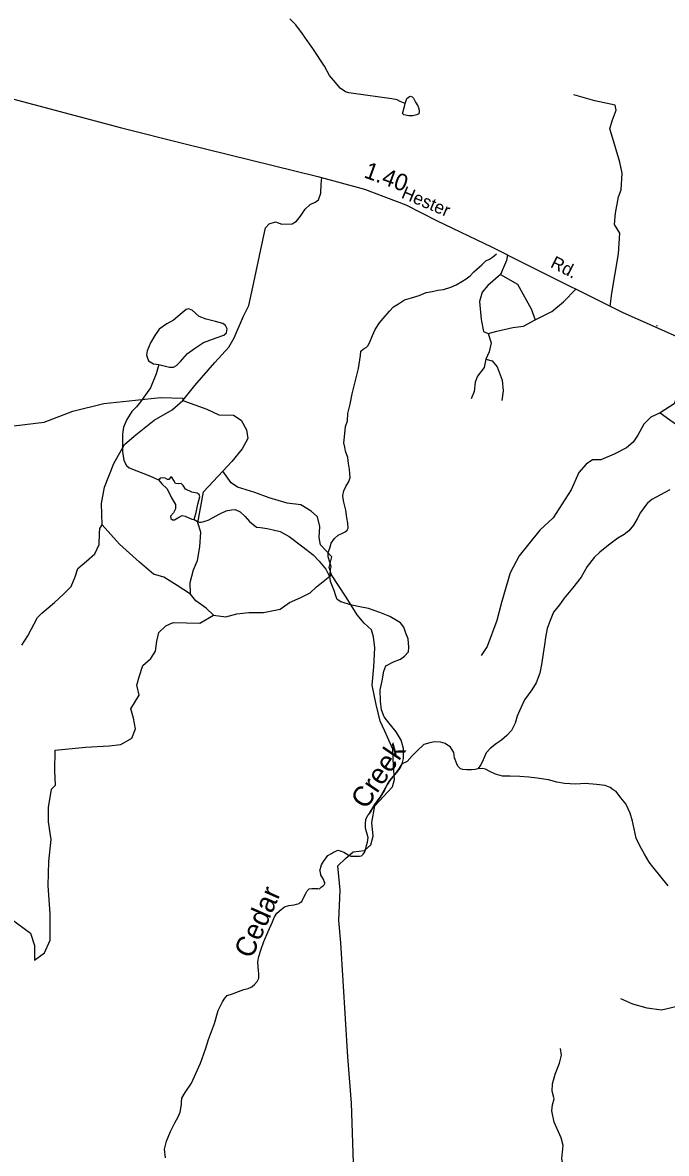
# Model space of a CAD drawing. Extents: x 2056842 to 2160602, y 826753 to 1016856.
# Drawn here: x 2105136 to 2109914, y 872458 to 880850 of the extents above; entities that cross this region are included whole.
import ezdxf

# ---------------------------------------------------------------- set-up
doc = ezdxf.new("R2010")
doc.units = 0
for name, color, linetype in [('Exist Hydrographic Creek Single Shore', 7, 'Continuous'), ('Exist Hydrographic Creek Single Shore Label', 7, 'Continuous'), ('Exist Hydrographic Misc Water Feature', 7, 'Continuous'), ('Exist Road Non-System Type 51', 7, 'Continuous'), ('Exist Road Secondary Mileage Hundredths English Label', 7, 'Continuous'), ('Exist Road Secondary Type 51 Attributed', 7, 'Continuous'), ('Exist Road Secondary Type 51 Label', 7, 'Continuous')]:
    doc.layers.add(name, color=color, linetype=linetype)

msp = doc.modelspace()

# ---------------------------------------------------------------- linework, layer by layer
at = {"layer": 'Exist Hydrographic Creek Single Shore'}
for points in [[(2107975.1, 880248.9), (2107938.9, 880263.4), (2107916.8, 880275.4), (2107876.8, 880285.2), (2107592.8, 880324.4), (2107556.9, 880328.2), (2107532.9, 880336.2), (2107492.5, 880364.1), (2107458.7, 880405.9), (2107414.4, 880457.8), (2107376, 880525.6), (2107289.9, 880657.4), (2107265.5, 880693.3), (2107213.2, 880767.1), (2107163.4, 880832.9), (2107119.1, 880876.8)], [(2107413.7, 876738), (2107417.7, 876754.3), (2107421.7, 876790.3), (2107425.4, 876810.2), (2107417.3, 876846.2), (2107403.3, 876886.1), (2107403.3, 876918), (2107415.2, 876950.2), (2107427.1, 876986.1), (2107450.7, 877020.3), (2107478.8, 877046.3), (2107510.6, 877060.5), (2107530.8, 877070.5), (2107544.5, 877082.4), (2107552.8, 877098.6), (2107548.6, 877134.5), (2107542.5, 877174.3), (2107534.2, 877230.6), (2107520, 877290.3), (2107512, 877332.4), (2107511.8, 877340.3), (2107519.7, 877374.3), (2107535.8, 877406.4), (2107555.5, 877438.5), (2107567.3, 877470.4), (2107565.4, 877502.6), (2107561.1, 877534.5), (2107555.1, 877578.6), (2107549.2, 877622.4), (2107532.8, 877670.3), (2107526.8, 877700.2), (2107520.6, 877732.2), (2107524.5, 877776.4), (2107532.3, 877852.4), (2107548.2, 877894.4), (2107550, 877948.5), (2107565.9, 878018.4), (2107581.6, 878094.5), (2107628.8, 878282.5), (2107642.6, 878378.7), (2107646.5, 878410.7), (2107662.6, 878426.5), (2107686.5, 878438.8), (2107698.5, 878450.7), (2107710.5, 878472.8), (2107732.3, 878528.7), (2107751.9, 878573), (2107783.7, 878620.9), (2107811.6, 878653.1), (2107859.7, 878709.2), (2107889.5, 878739.4), (2107925.5, 878763.3), (2107971.4, 878793.5), (2108023.2, 878807.8), (2108079.3, 878823.7), (2108130.9, 878846), (2108175.1, 878854.2), (2108218.9, 878864.5), (2108259, 878868.6), (2108314.9, 878886.8), (2108354.9, 878902.7), (2108396.8, 878928.7), (2108428.6, 878947.1), (2108456.7, 878971.1), (2108484.5, 878999.1), (2108544.4, 879053.3), (2108574.1, 879081.6), (2108600.3, 879093.5), (2108624.3, 879109.4), (2108654, 879133.7)], [(2107953.9, 875348.1), (2107963.9, 875389.9), (2107963.5, 875464), (2107945.4, 875523.8), (2107909.3, 875585.9), (2107855.2, 875653.6), (2107819.1, 875697.7), (2107798.8, 875749.6), (2107792.6, 875813.4), (2107790.4, 875897.4), (2107804.3, 875965.4), (2107817.9, 876037.6), (2107831.8, 876077.4), (2107887.5, 876105.7), (2107939.5, 876126), (2107969.5, 876148), (2107999.3, 876179.9), (2108003.3, 876215.9), (2107997, 876276.1), (2107980.9, 876320), (2107964.7, 876364), (2107940.8, 876395.7), (2107916.8, 876409.6), (2107860.7, 876441.6), (2107786.5, 876473.3), (2107702.5, 876501), (2107638.5, 876514.8), (2107578.3, 876526.5), (2107498.5, 876552.5), (2107470.3, 876568.5), (2107460.3, 876596.2), (2107448, 876636.2), (2107435.9, 876666.3), (2107421.8, 876702), (2107417.7, 876726.1), (2107413.7, 876738)], [(2108514.3, 875311.9), (2108494.6, 875308), (2108468.3, 875303.9), (2108432.3, 875303.7), (2108402.3, 875307.8), (2108386.3, 875311.4), (2108365.8, 875331.6), (2108357.8, 875349.4), (2108342.2, 875393.6), (2108335.7, 875433.5), (2108311.7, 875473.3), (2108273.3, 875500.9), (2108237.9, 875509.2), (2108193.4, 875513), (2108157.7, 875504.7), (2108114, 875492.6), (2108063.8, 875446.3), (2108026, 875408.6), (2107990.2, 875366.1), (2107953.9, 875348.1)], [(2107652.1, 874667.3), (2107664.1, 874679.2), (2107672.3, 874691.1), (2107680.2, 874711.3), (2107688.1, 874743.3), (2107695.8, 874767.4), (2107699.8, 874803.4), (2107693.8, 874827.2), (2107689.5, 874843.4), (2107681.5, 874871.1), (2107681.6, 874903.2), (2107683.2, 874935.4), (2107695.3, 874963.3), (2107699.3, 874967.2), (2107707.1, 874979.2), (2107719.2, 874995.3), (2107727.1, 875011.2), (2107748.9, 875047.5), (2107788.7, 875101.5), (2107820.6, 875153.7), (2107844.5, 875197.8), (2107860.5, 875225.7), (2107910.3, 875286), (2107934.2, 875318), (2107953.9, 875348.1)], [(2106197.5, 872424.9), (2106189.3, 872489), (2106193.3, 872509), (2106203, 872548.8), (2106234.7, 872621), (2106266.5, 872685), (2106290.4, 872729.1), (2106304.3, 872765.2), (2106314.3, 872821.1), (2106314, 872837.2), (2106317.9, 872869.3), (2106342, 872909.1), (2106389.7, 872979.3), (2106421.4, 873051.5), (2106455.1, 873127.6), (2106492.7, 873231.8), (2106516.5, 873303.9), (2106560.3, 873422), (2106587.9, 873517.9), (2106605.7, 873554), (2106619.7, 873581.9), (2106635.7, 873610.1), (2106653.5, 873630.1), (2106693.5, 873642.4), (2106737.5, 873660.5), (2106777.5, 873674.5), (2106809.5, 873682.7), (2106837.3, 873694.9), (2106857.3, 873710.9), (2106877.2, 873734.7), (2106881.3, 873742.9), (2106889.2, 873758.8), (2106889.2, 873790.9), (2106887, 873814.9), (2106885, 873842.9), (2106880.8, 873878.7), (2106888.5, 873918.9), (2106904.6, 873966.8), (2106926.3, 874031), (2106958, 874105.1), (2106989.7, 874177), (2107005.8, 874213.1), (2107023.5, 874241.3), (2107055.6, 874269.5), (2107079.6, 874289.3), (2107111.6, 874297.5), (2107151.4, 874303.6), (2107169.5, 874307.8), (2107187.3, 874311.7), (2107195.4, 874319.7), (2107207.4, 874327.7), (2107223.1, 874359.9), (2107239.1, 874388.1), (2107249, 874407.9), (2107263.1, 874422), (2107283.2, 874423.9), (2107315, 874424.2), (2107327.2, 874424.3), (2107338.9, 874422.1), (2107346.9, 874428.2), (2107355, 874436.2), (2107366.9, 874444.2), (2107375, 874452.2), (2107378.7, 874460.3), (2107378.9, 874468.2), (2107374.8, 874476.5), (2107370.8, 874488.4), (2107358.7, 874508.3), (2107350.5, 874524.2), (2107346.7, 874544.3), (2107342.6, 874554.2), (2107354.4, 874600.3), (2107368.4, 874624.3), (2107400.1, 874668.2), (2107428.3, 874684.4), (2107444.3, 874692.6), (2107460.2, 874700.4), (2107476.1, 874708.7), (2107492.1, 874704.7), (2107520, 874692.7), (2107540.1, 874680.8), (2107552.2, 874674.9), (2107572.3, 874663), (2107580.1, 874662.9), (2107608.3, 874662.9), (2107620.2, 874663), (2107636.2, 874663), (2107652.1, 874667.3)]]:
    msp.add_lwpolyline(points, dxfattribs=at)
at = {"layer": 'Exist Hydrographic Misc Water Feature'}
msp.add_line((2109840.1, 878603.3), (2109843.6, 878596.9), dxfattribs=at)
for points in [[(2107975.1, 880248.9), (2107988.5, 880285.3), (2108006.7, 880302.4), (2108015.2, 880303.6), (2108026.2, 880299.9), (2108035.9, 880287.8), (2108051.7, 880258.6), (2108068.7, 880231.8), (2108076, 880212.4), (2108079.7, 880190.5), (2108076, 880173.5), (2108062.6, 880164.9), (2108031, 880158.9), (2108003.1, 880158.9), (2107965.4, 880164.9), (2107956.9, 880172.2), (2107956.9, 880183.2), (2107969.1, 880227), (2107975.1, 880248.9)], [(2106146.8, 878312.3), (2106227.1, 878292.8), (2106255, 878294), (2106279.3, 878306.2), (2106308.5, 878335.4), (2106359.6, 878393.7), (2106411.8, 878430.2), (2106477.4, 878475.2), (2106572.3, 878510.5), (2106630.6, 878531.2), (2106648.8, 878548.2), (2106653.7, 878576.2), (2106642.7, 878602.9), (2106622.1, 878617.5), (2106567.4, 878632.1), (2106498.1, 878647.9), (2106445.8, 878668.6), (2106393.6, 878716), (2106368.1, 878725.7), (2106348.6, 878720.9), (2106320.7, 878695.3), (2106255, 878641.8), (2106206.4, 878613.9), (2106150.5, 878573.7), (2106117.7, 878528.7), (2106084.9, 878474), (2106060.6, 878413.2), (2106054.5, 878385.2), (2106059.3, 878367), (2106070.3, 878339), (2106106.7, 878317.1), (2106146.8, 878312.3)], [(2106146.8, 878312.3), (2106127.4, 878244.1), (2106086.1, 878140.5), (2106011.9, 878035.9), (2105980.3, 877999.5), (2105946.4, 877963.5), (2105908.9, 877903.5), (2105885.1, 877847.4), (2105876.9, 877795.6), (2105877.1, 877727.4), (2105877.1, 877667.3), (2105888, 877599.4), (2105907.4, 877564.1), (2105925.6, 877545.8), (2106084.9, 877483.8), (2106145.6, 877457.1)], [(2106409.4, 877161.5), (2106422.8, 877213.8), (2106437.3, 877275.9), (2106450.7, 877329.4), (2106445.8, 877347.6), (2106431.3, 877358.6), (2106391.2, 877365.9), (2106343.8, 877387.7), (2106328, 877414.5), (2106313.4, 877429.1), (2106292.7, 877427.9), (2106269.6, 877430.3), (2106258.7, 877452.2), (2106246.5, 877471.7), (2106235.6, 877479), (2106230.7, 877471.7), (2106222.2, 877459.5), (2106211.3, 877459.5), (2106193, 877468), (2106173.6, 877470.4), (2106157.8, 877468), (2106151.7, 877461.9), (2106145.6, 877457.1)], [(2106145.6, 877457.1), (2106169.9, 877427.9), (2106207.6, 877390.2), (2106241.7, 877322.1), (2106269.6, 877274.6), (2106270.8, 877241.8), (2106256.2, 877212.6), (2106234.4, 877187.1), (2106235.6, 877168.8), (2106247.7, 877159.1), (2106263.5, 877160.3), (2106289.1, 877174.9), (2106320.7, 877191.9), (2106342.5, 877187.1), (2106392.4, 877165.2), (2106409.4, 877161.5)], [(2109940.2, 877383.1), (2109869.7, 877345.4), (2109806.5, 877311.4), (2109773.7, 877284.6), (2109760.4, 877268.8), (2109722, 877213.4), (2109698.2, 877167.5), (2109670.4, 877119.4), (2109634.3, 877079.4), (2109600.6, 877051.2), (2109554.7, 877022.8), (2109484.8, 876973), (2109419.2, 876920.4), (2109379, 876880.3), (2109325.5, 876814.2), (2109281.4, 876734), (2109217.6, 876651.9), (2109156.1, 876577.7), (2109120.4, 876529.5), (2109076.5, 876473.6), (2109052.5, 876413.6), (2109028.5, 876353.5), (2109017.3, 876285.5), (2109009.5, 876233.5), (2108999.6, 876169.2), (2108987.7, 876085.4), (2108973.6, 876021.4), (2108948, 875951.4), (2108916.4, 875899), (2108860.8, 875823.1), (2108822.7, 875742.8), (2108807.3, 875702.9), (2108791.3, 875650.5), (2108765.3, 875596.9), (2108729.6, 875560.5), (2108689.6, 875524.3), (2108653.7, 875500.2), (2108605.5, 875464), (2108576, 875432), (2108554.3, 875378.1), (2108538.1, 875342), (2108514.3, 875311.9)], [(2106409.4, 877161.5), (2106432.8, 877147.3), (2106448.6, 877143.3), (2106460.9, 877143.1), (2106480.8, 877147.3), (2106512.6, 877157.6), (2106549.1, 877177.5), (2106594.8, 877201.5), (2106646.7, 877225.6), (2106686.9, 877233.8), (2106714.7, 877236.1), (2106750.8, 877220.1), (2106786.5, 877184.2), (2106820.8, 877148.1), (2106873, 877104.5), (2106900.7, 877102.8), (2106951, 877094.8), (2106994.6, 877084.9), (2107047.1, 877072.9), (2107115.2, 877037.4), (2107215.3, 876959.8), (2107291.6, 876899.9), (2107337.5, 876854), (2107386.1, 876794.3), (2107413.8, 876738.2)], [(2107953.9, 875348.1), (2107934.6, 875318.1), (2107910.4, 875286.1), (2107860.6, 875226), (2107844.8, 875197.9), (2107820.8, 875153.6), (2107788.8, 875101.7), (2107749.2, 875047.6), (2107727.5, 875011.6), (2107719.3, 874995.4), (2107707.4, 874979.7), (2107699.4, 874967.5)], [(2109926.9, 874444.9), (2109812.5, 874584), (2109786.2, 874620.1), (2109752, 874678.1), (2109715.9, 874741.9), (2109689.4, 874797.9), (2109675.3, 874865.8), (2109663.2, 874923.6), (2109645.1, 874983.5), (2109629.4, 875015.6), (2109612.7, 875051.4), (2109577.1, 875097.3), (2109540.6, 875143), (2109520.3, 875157.1), (2109496.7, 875173.3), (2109458.5, 875189.2), (2109394.4, 875196.8), (2109310.3, 875202.7), (2109242.4, 875198.4), (2109158.3, 875204.1), (2109100.1, 875213.8), (2109038.6, 875229.7), (2108954.1, 875243.2), (2108894.2, 875251.1), (2108826.6, 875254.9), (2108754.6, 875256.8), (2108698.4, 875258.5), (2108646.3, 875272.4), (2108602.5, 875292.1), (2108570.3, 875310.3), (2108550.4, 875314.1), (2108514.3, 875311.9)]]:
    msp.add_lwpolyline(points, dxfattribs=at)
at = {"layer": 'Exist Road Non-System Type 51'}
for points in [[(2109497.6, 878743.9), (2109508.2, 878842.1), (2109559.6, 879133.1), (2109569.1, 879287.1), (2109528.2, 879352.7), (2109535.8, 879436.4), (2109558.6, 879556.2), (2109579.5, 879609.4), (2109585.2, 879733), (2109568.1, 879812.9), (2109506.3, 880023), (2109494.9, 880061), (2109512, 880121.9), (2109542.5, 880199.8), (2109534.9, 880236), (2109382.8, 880270.2), (2109227, 880313.9)], [(2106325.8, 878044.9), (2106415.1, 878157.1), (2106563.4, 878326.4), (2106666.9, 878441.4), (2106704.9, 878511.7), (2106775.2, 878671.5), (2106815.1, 878749.4), (2106843.6, 878886.3), (2106918.7, 879235.3), (2106937.7, 879326.5), (2106966.2, 879357), (2107011.8, 879370.3), (2107059.3, 879353.2), (2107137.2, 879357), (2107169.5, 879376), (2107198, 879414), (2107232.2, 879465.4), (2107270.2, 879499.6), (2107308.2, 879516.7), (2107332.9, 879533.8), (2107348.1, 879583.3), (2107351.9, 879649.8), (2107357.6, 879699.4)], [(2108733.9, 879127.1), (2108728.2, 879084.6), (2108682.6, 878980)], [(2108682.6, 878980), (2108587.6, 878898.2), (2108547.7, 878848.8), (2108526.8, 878780.3), (2108538.2, 878647.2), (2108557.2, 878557.9), (2108591.4, 878542.6)], [(2108682.6, 878980), (2108809.9, 878907.7), (2108849.8, 878837.4), (2108910.6, 878725.2), (2108941, 878645.3)], [(2108941, 878645.3), (2109063.6, 878707.1), (2109151, 878777.5), (2109241.1, 878872.5)], [(2108591.4, 878542.6), (2108655, 878560.7), (2108774.8, 878587.3), (2108852.7, 878596.8), (2108941, 878645.3)], [(2108591.4, 878542.6), (2108613.2, 878473.2), (2108598, 878406.7), (2108573.3, 878351.5)], [(2110228.4, 878433.8), (2110180, 878401.9), (2110104, 878352.5), (2110035.6, 878227), (2110003.3, 878109.1), (2109971, 878019.7), (2109868.3, 877955.1)], [(2108573.3, 878351.5), (2108561.9, 878290.7), (2108512.5, 878226), (2108495.4, 878180.4), (2108487.8, 878112), (2108465, 878056.8)], [(2108573.3, 878351.5), (2108620.8, 878340.1), (2108656.9, 878296.4), (2108694.9, 878195.6), (2108702.5, 878117.7), (2108693, 878045.4)], [(2103989.5, 877340.4), (2104204.2, 877405.1), (2104382.8, 877481.1), (2104546.3, 877483), (2104563.4, 877625.6), (2104571, 877774), (2104639.4, 877838.6), (2104816.1, 877867.1), (2105070.7, 877857.6), (2105296.8, 877884.2), (2105507.8, 877966), (2105738.7, 878024), (2105974.3, 878046.8), (2106160.5, 878067.7), (2106325.8, 878063.9), (2106325.8, 878044.9)], [(2105726.3, 877121.7), (2105722.5, 877281.5), (2105743.4, 877403.2), (2105811.8, 877578.1), (2105892.6, 877717.9), (2105962.9, 877780.6), (2106111.1, 877900.4), (2106246, 877976.5), (2106325.8, 878044.9)], [(2106325.8, 878044.9), (2106504.4, 877982.2), (2106591.9, 877938.4), (2106700.2, 877936.5), (2106757.2, 877900.4), (2106797.1, 877828.2), (2106808.5, 877763.5), (2106764.8, 877687.4), (2106688.8, 877592.4), (2106621.3, 877521.1)], [(2109868.3, 877955.1), (2109799, 877921.8), (2109747.7, 877870.5), (2109702.1, 877788.7), (2109667.9, 877735.5), (2109618.5, 877693.6), (2109525.4, 877646.1), (2109426.5, 877606.1), (2109365.7, 877604.2), (2109318.2, 877573.8), (2109263.1, 877511.1), (2109208, 877381.8), (2109074, 877175.5), (2108975.2, 877084.2), (2108821.3, 876892.1), (2108753.9, 876765.7), (2108691.1, 876547), (2108655, 876412), (2108582.8, 876219.9), (2108539.1, 876153.4)], [(2109868.3, 877955.1), (2109939.6, 877902.8), (2110030.8, 877838.1), (2110152.4, 877798.2), (2110224.6, 877796.3), (2110308.2, 877815.3), (2110369.1, 877811.5), (2110437.5, 877760.2)], [(2106382.8, 876609.3), (2106379, 876694.9), (2106403.7, 876789.9), (2106434.1, 876858.4), (2106451.2, 876959.2), (2106458.8, 877069.4), (2106437, 877137), (2106478.8, 877367), (2106621.3, 877521.1)], [(2107428, 876751.9), (2107410.9, 876805.1), (2107429.9, 876885), (2107346.2, 876974.4), (2107336.7, 877027.6), (2107342.4, 877109.4), (2107323.4, 877181.6), (2107277.8, 877223.5), (2107201.8, 877271), (2107099.2, 877284.3), (2106965.3, 877323.3), (2106860.7, 877363.2), (2106731.5, 877401.3), (2106684, 877433.6), (2106621.3, 877521.1)], [(2105129.6, 876229.9), (2105174.3, 876298.4), (2105246.5, 876435.3), (2105277.8, 876467.6), (2105371.9, 876546.5), (2105438.4, 876607.4), (2105495.4, 876664.4), (2105525.8, 876736.7), (2105546.7, 876799.4), (2105609.9, 876854.1), (2105672.6, 876907.3), (2105703, 876977.7), (2105706.8, 877059.5), (2105708.7, 877095.6), (2105726.3, 877121.7)], [(2106382.8, 876609.3), (2106282.1, 876672), (2106185.2, 876734.8), (2106107.3, 876757.6), (2106002.8, 876845.1), (2105854.6, 876978.2), (2105726.3, 877121.7)], [(2106552, 876451.5), (2106645.1, 876440), (2106724.9, 876462.9), (2106814.2, 876472.4), (2106924.4, 876472.4), (2107047.9, 876497.1), (2107117.3, 876545.6), (2107200.9, 876583.6), (2107269.3, 876617.8), (2107316.8, 876663.5), (2107428, 876751.9)], [(2107591.4, 872387.9), (2107577.1, 872831.9), (2107548.6, 873176.1), (2107498.3, 874021.3), (2107484, 874185.8), (2107493.5, 874412.1), (2107476.4, 874592.7), (2107533.4, 874646), (2107590.4, 874697.3), (2107674, 874706.8), (2107721.5, 874748.6), (2107738.6, 874811.4), (2107728.2, 874913.1), (2107749.1, 875038.6), (2107882.1, 875177.4), (2107895.4, 875232.6), (2107887.8, 875331.5), (2107884, 875457), (2107823.2, 875592), (2107790, 875665.2), (2107759.5, 875788.8), (2107731, 875933.3), (2107742.4, 876068.3), (2107750, 876209), (2107740.5, 876292.7), (2107726.3, 876343.1), (2107671.2, 876392.5), (2107619.9, 876455.3), (2107538.2, 876586.5), (2107428, 876751.9)], [(2106552, 876451.5), (2106498.7, 876504.7), (2106420.8, 876557.9), (2106382.8, 876609.3)], [(2105005.2, 874232.4), (2105193.3, 874091.7), (2105223.7, 874002.3), (2105223.7, 873892), (2105297.8, 873947.2), (2105339.6, 874040.3), (2105339.6, 874236.2), (2105324.4, 874445.4), (2105330.1, 874624.1), (2105348.2, 874786.7), (2105327.3, 874917.9), (2105329.2, 875026.3), (2105350.1, 875161.3), (2105380.5, 875191.7), (2105374.8, 875298.2), (2105377.6, 875451.3), (2105603.7, 875474.1), (2105778.6, 875481.7), (2105866, 875493.1), (2105947.7, 875538.7), (2105974.3, 875609.1), (2105959.1, 875687), (2105940.1, 875757.4), (2105999.9, 875859.1), (2105984.7, 875933.3), (2105999.9, 875996), (2106028.4, 876079.7), (2106087.3, 876131.1), (2106121.5, 876186.2), (2106133, 876258.5), (2106146.3, 876323.1), (2106199.5, 876372.5), (2106252.7, 876399.2), (2106452.2, 876393.5), (2106552, 876451.5)], [(2110238.4, 872923.2), (2110200.5, 872981.1), (2110272.7, 873388), (2110265.1, 873433.7), (2110238.5, 873452.7), (2110044.7, 873486.9), (2109995.3, 873547.8), (2109877.5, 873521.1), (2109771, 873536.3), (2109664.6, 873566.8), (2109577.2, 873604.8)], [(2109195.2, 872279.5), (2109152.5, 872345), (2109139.2, 872419.2), (2109146.8, 872516.2), (2109133.5, 872575.1), (2109082.2, 872689.2), (2109064.2, 872773.8), (2109069.9, 872819.5), (2109081.3, 872863.2), (2109066.1, 872920.2), (2109068, 872975.4), (2109088.9, 873045.8), (2109121.2, 873127.5), (2109136.4, 873188.4), (2109128.8, 873237.8)]]:
    msp.add_lwpolyline(points, dxfattribs=at)
at = {"layer": 'Exist Road Secondary Type 51 Attributed'}
msp.add_lwpolyline([(2104100.7, 880519.5), (2104430.4, 880441.8), (2104909.3, 880323.9), (2105869.8, 880068.1), (2106333.5, 879952.1), (2107326.3, 879707.8), (2107674, 879614.6), (2107979.5, 879496.3), (2108213.2, 879379.3), (2108615.6, 879186.8), (2108856.9, 879065.1), (2109589.9, 878697.7), (2110032.1, 878502.3), (2110383.7, 878379.6), (2110888.6, 878198.5), (2111059.2, 878126.7)], dxfattribs=at)

# ---------------------------------------------------------------- texts
at = {"layer": 'Exist Hydrographic Creek Single Shore Label'}
for s, rotation, p in [('Creek', 56.08937, (2107685.6, 875004.6)), ('Cedar', 66.15967, (2106836.6, 873896.6))]:
    msp.add_text(s, height=150, rotation=rotation, dxfattribs=at).set_placement(p)
at = {"layer": 'Exist Road Secondary Mileage Hundredths English Label'}
msp.add_text('1.40', height=125, rotation=340.03497, dxfattribs=at).set_placement((2107662, 879703.1))
at = {"layer": 'Exist Road Secondary Type 51 Label'}
for s, rotation, p in [('Hester', 337.036, (2107940.3, 879551.7)), ('Rd.', 332.952, (2109046.6, 879037.7))]:
    msp.add_text(s, height=95, rotation=rotation, dxfattribs=at).set_placement(p)

doc.saveas('drawing.dxf')
